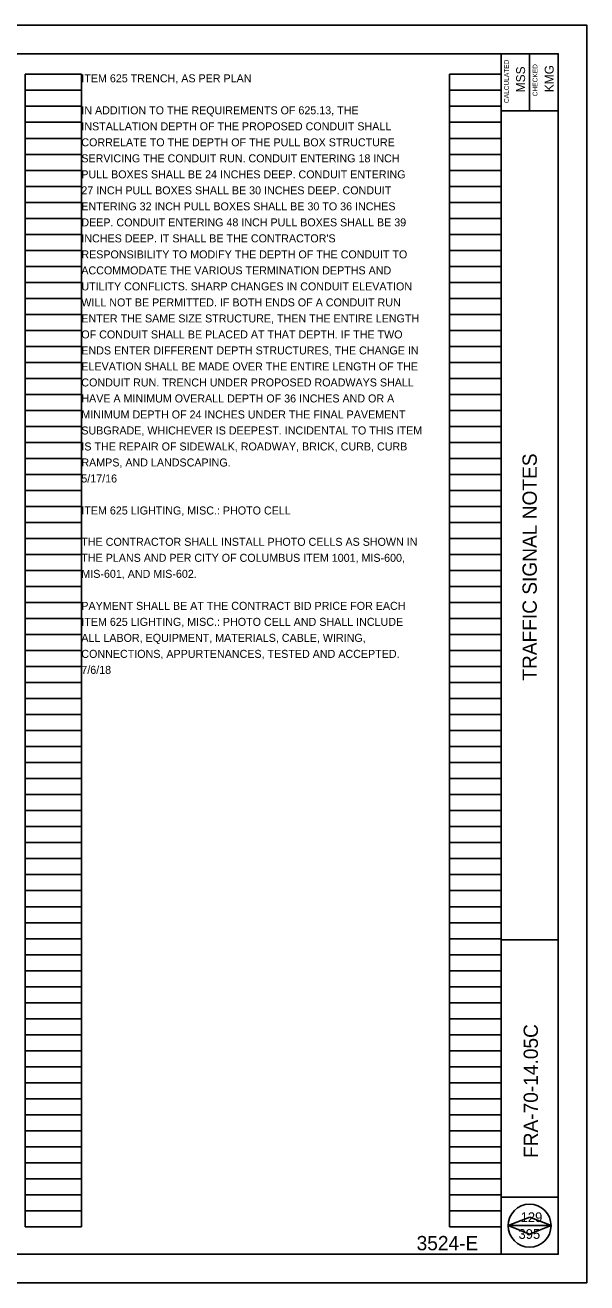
# Model space of a CAD drawing. Extents: x -25.6 to 66.7, y -23.1 to 37.2.
# Drawn here: x 23.67 to 33.49, y -7.51 to 14.49 of the extents above; entities that cross this region are included whole.
import ezdxf

# ---------------------------------------------------------------- set-up
doc = ezdxf.new("R2010")
doc.units = 0
for name, color, linetype in [('Level 63', 7, 'Continuous'), ('PF_P_Text', 7, 'Continuous'), ('SC_Scratch1', 7, 'Continuous'), ('SH_Cut_Line', 7, 'Continuous'), ('SH_Data', 7, 'Continuous'), ('SH_Text', 7, 'Continuous')]:
    doc.layers.add(name, color=color, linetype=linetype)

msp = doc.modelspace()

# ---------------------------------------------------------------- linework, layer by layer
at = {"layer": 'Level 63'}
msp.add_line((32.119, -6.508), (32.869, -6.508), dxfattribs=at)
msp.add_circle((32.494, -6.508), 0.375, dxfattribs=at)
at = {"layer": 'PF_P_Text'}
for p, q in [((31.994, -7.008), (31.994, 13.992)), ((32.494, 13.992), (32.494, 12.992)), ((31.994, 12.992), (32.994, 12.992)), ((31.994, -1.508), (32.994, -1.508)), ((31.994, -6.008), (32.994, -6.008))]:
    msp.add_line(p, q, dxfattribs=at)
msp.add_lwpolyline([(1.494, 13.992), (32.994, 13.992), (32.994, -7.008), (1.494, -7.008)], close=True, dxfattribs=at)
at = {"layer": 'SC_Scratch1'}
for p, q in [((23.674, -6.528), (23.674, 13.632)), ((23.674, 13.632), (24.654, 13.632)), ((24.654, -6.528), (24.654, 13.632)), ((31.094, -6.528), (31.094, 13.632)), ((31.094, 13.632), (31.994, 13.632)), ((31.994, -6.528), (31.994, 13.632)), ((23.674, 13.352), (24.654, 13.352)), ((31.094, 13.352), (31.994, 13.352)), ((23.674, 13.072), (24.654, 13.072)), ((31.094, 13.072), (31.994, 13.072)), ((23.674, 12.792), (24.654, 12.792)), ((31.094, 12.792), (31.994, 12.792)), ((23.674, 12.512), (24.654, 12.512)), ((31.094, 12.512), (31.994, 12.512)), ((23.674, 12.232), (24.654, 12.232)), ((31.094, 12.232), (31.994, 12.232)), ((23.674, 11.952), (24.654, 11.952)), ((31.094, 11.952), (31.994, 11.952)), ((23.674, 11.672), (24.654, 11.672)), ((31.094, 11.672), (31.994, 11.672)), ((23.674, 11.392), (24.654, 11.392)), ((31.094, 11.392), (31.994, 11.392)), ((23.674, 11.112), (24.654, 11.112)), ((31.094, 11.112), (31.994, 11.112)), ((23.674, 10.832), (24.654, 10.832)), ((31.094, 10.832), (31.994, 10.832)), ((23.674, 10.552), (24.654, 10.552)), ((31.094, 10.552), (31.994, 10.552)), ((23.674, 10.272), (24.654, 10.272)), ((31.094, 10.272), (31.994, 10.272)), ((23.674, 9.992), (24.654, 9.992)), ((31.094, 9.992), (31.994, 9.992)), ((23.674, 9.712), (24.654, 9.712)), ((31.094, 9.712), (31.994, 9.712)), ((23.674, 9.432), (24.654, 9.432)), ((31.094, 9.432), (31.994, 9.432)), ((23.674, 9.152), (24.654, 9.152)), ((31.094, 9.152), (31.994, 9.152)), ((23.674, 8.872), (24.654, 8.872)), ((31.094, 8.872), (31.994, 8.872)), ((23.674, 8.592), (24.654, 8.592)), ((31.094, 8.592), (31.994, 8.592)), ((23.674, 8.312), (24.654, 8.312)), ((31.094, 8.312), (31.994, 8.312)), ((23.674, 8.032), (24.654, 8.032)), ((31.094, 8.032), (31.994, 8.032)), ((23.674, 7.752), (24.654, 7.752)), ((31.094, 7.752), (31.994, 7.752)), ((23.674, 7.472), (24.654, 7.472)), ((31.094, 7.472), (31.994, 7.472)), ((23.674, 7.192), (24.654, 7.192)), ((31.094, 7.192), (31.994, 7.192)), ((23.674, 6.912), (24.654, 6.912)), ((31.094, 6.912), (31.994, 6.912)), ((23.674, 6.632), (24.654, 6.632)), ((31.094, 6.632), (31.994, 6.632)), ((23.674, 6.352), (24.654, 6.352)), ((31.094, 6.352), (31.994, 6.352)), ((23.674, 6.072), (24.654, 6.072)), ((31.094, 6.072), (31.994, 6.072)), ((23.674, 5.792), (24.654, 5.792)), ((31.094, 5.792), (31.994, 5.792)), ((23.674, 5.512), (24.654, 5.512)), ((31.094, 5.512), (31.994, 5.512)), ((23.674, 5.232), (24.654, 5.232)), ((31.094, 5.232), (31.994, 5.232)), ((23.674, 4.952), (24.654, 4.952)), ((31.094, 4.952), (31.994, 4.952)), ((23.674, 4.672), (24.654, 4.672)), ((31.094, 4.672), (31.994, 4.672)), ((23.674, 4.392), (24.654, 4.392)), ((31.094, 4.392), (31.994, 4.392)), ((23.674, 4.112), (24.654, 4.112)), ((31.094, 4.112), (31.994, 4.112)), ((23.674, 3.832), (24.654, 3.832)), ((31.094, 3.832), (31.994, 3.832)), ((23.674, 3.552), (24.654, 3.552)), ((31.094, 3.552), (31.994, 3.552)), ((23.674, 3.272), (24.654, 3.272)), ((31.094, 3.272), (31.994, 3.272)), ((23.674, 2.992), (24.654, 2.992)), ((31.094, 2.992), (31.994, 2.992)), ((23.674, 2.712), (24.654, 2.712)), ((31.094, 2.712), (31.994, 2.712)), ((23.674, 2.432), (24.654, 2.432)), ((31.094, 2.432), (31.994, 2.432)), ((23.674, 2.152), (24.654, 2.152)), ((31.094, 2.152), (31.994, 2.152)), ((23.674, 1.872), (24.654, 1.872)), ((31.094, 1.872), (31.994, 1.872)), ((23.674, 1.592), (24.654, 1.592)), ((31.094, 1.592), (31.994, 1.592)), ((23.674, 1.312), (24.654, 1.312)), ((31.094, 1.312), (31.994, 1.312)), ((23.674, 1.032), (24.654, 1.032)), ((31.094, 1.032), (31.994, 1.032)), ((23.674, 0.752), (24.654, 0.752)), ((31.094, 0.752), (31.994, 0.752)), ((23.674, 0.472), (24.654, 0.472)), ((31.094, 0.472), (31.994, 0.472)), ((23.674, 0.192), (24.654, 0.192)), ((31.094, 0.192), (31.994, 0.192)), ((23.674, -0.088), (24.654, -0.088)), ((31.094, -0.088), (31.994, -0.088)), ((23.674, -0.368), (24.654, -0.368)), ((31.094, -0.368), (31.994, -0.368)), ((23.674, -0.648), (24.654, -0.648)), ((31.094, -0.648), (31.994, -0.648)), ((23.674, -0.928), (24.654, -0.928)), ((31.094, -0.928), (31.994, -0.928)), ((23.674, -1.208), (24.654, -1.208)), ((31.094, -1.208), (31.994, -1.208)), ((23.674, -1.488), (24.654, -1.488)), ((31.094, -1.488), (31.994, -1.488)), ((23.674, -1.768), (24.654, -1.768)), ((31.094, -1.768), (31.994, -1.768)), ((23.674, -2.048), (24.654, -2.048)), ((31.094, -2.048), (31.994, -2.048)), ((23.674, -2.328), (24.654, -2.328)), ((31.094, -2.328), (31.994, -2.328)), ((23.674, -2.608), (24.654, -2.608)), ((31.094, -2.608), (31.994, -2.608)), ((23.674, -2.888), (24.654, -2.888)), ((31.094, -2.888), (31.994, -2.888)), ((23.674, -3.168), (24.654, -3.168)), ((31.094, -3.168), (31.994, -3.168)), ((23.674, -3.448), (24.654, -3.448)), ((31.094, -3.448), (31.994, -3.448)), ((23.674, -3.728), (24.654, -3.728)), ((31.094, -3.728), (31.994, -3.728)), ((23.674, -4.008), (24.654, -4.008)), ((31.094, -4.008), (31.994, -4.008)), ((23.674, -4.288), (24.654, -4.288)), ((31.094, -4.288), (31.994, -4.288)), ((23.674, -4.568), (24.654, -4.568)), ((31.094, -4.568), (31.994, -4.568)), ((23.674, -4.848), (24.654, -4.848)), ((31.094, -4.848), (31.994, -4.848)), ((23.674, -5.128), (24.654, -5.128)), ((31.094, -5.128), (31.994, -5.128)), ((23.674, -5.408), (24.654, -5.408)), ((31.094, -5.408), (31.994, -5.408)), ((23.674, -5.688), (24.654, -5.688)), ((31.094, -5.688), (31.994, -5.688)), ((23.674, -5.968), (24.654, -5.968)), ((31.094, -5.968), (31.994, -5.968)), ((23.674, -6.248), (24.654, -6.248)), ((31.094, -6.248), (31.994, -6.248)), ((32.119, -6.508), (32.495, -6.36)), ((32.495, -6.36), (32.869, -6.508)), ((23.674, -6.528), (24.654, -6.528)), ((31.094, -6.528), (31.994, -6.528)), ((32.49, -6.654), (32.119, -6.508)), ((32.869, -6.508), (32.49, -6.654))]:
    msp.add_line(p, q, dxfattribs=at)
at = {"layer": 'SH_Cut_Line'}
msp.add_lwpolyline([(-0.506, -7.508), (33.494, -7.508), (33.494, 14.492), (-0.506, 14.492)], close=True, dxfattribs=at)

# ---------------------------------------------------------------- texts
at = {"layer": 'Level 63'}
for s, height, p in [('CALCULATED', 0.0833, (32.13, 13.129)), ('MSS', 0.156, (32.414, 13.317)), ('CHECKED', 0.0833, (32.63, 13.248)), ('KMG', 0.156, (32.914, 13.319)), ('TRAFFIC SIGNAL NOTES', 0.25, (32.619, 3.025)), ('FRA-70-14.05C', 0.25, (32.639, -5.324))]:
    msp.add_text(s, height=height, rotation=90, dxfattribs=at).set_placement(p)
at = {"layer": 'SH_Data'}
msp.add_text('3524-E', height=0.25, rotation=359.9999, dxfattribs=at).set_placement((30.517, -6.938))
at = {"layer": 'SH_Text'}
for s, height, p in [('ITEM 625 TRENCH, AS PER PLAN', 0.14, (24.654, 13.492)), ('IN ADDITION TO THE REQUIREMENTS OF 625.13, THE ', 0.14, (24.654, 12.932)), ('INSTALLATION DEPTH OF THE PROPOSED CONDUIT SHALL ', 0.14, (24.654, 12.652)), ('CORRELATE TO THE DEPTH OF THE PULL BOX STRUCTURE ', 0.14, (24.654, 12.372)), ('SERVICING THE CONDUIT RUN. CONDUIT ENTERING 18 INCH ', 0.14, (24.654, 12.092)), ('PULL BOXES SHALL BE 24 INCHES DEEP. CONDUIT ENTERING ', 0.14, (24.654, 11.812)), ('27 INCH PULL BOXES SHALL BE 30 INCHES DEEP. CONDUIT ', 0.14, (24.654, 11.532)), ('ENTERING 32 INCH PULL BOXES SHALL BE 30 TO 36 INCHES ', 0.14, (24.654, 11.252)), ('DEEP. CONDUIT ENTERING 48 INCH PULL BOXES SHALL BE 39 ', 0.14, (24.654, 10.972)), ("INCHES DEEP. IT SHALL BE THE CONTRACTOR'S ", 0.14, (24.654, 10.692)), ('RESPONSIBILITY TO MODIFY THE DEPTH OF THE CONDUIT TO ', 0.14, (24.654, 10.412)), ('ACCOMMODATE THE VARIOUS TERMINATION DEPTHS AND ', 0.14, (24.654, 10.132)), ('UTILITY CONFLICTS. SHARP CHANGES IN CONDUIT ELEVATION ', 0.14, (24.654, 9.852)), ('WILL NOT BE PERMITTED. IF BOTH ENDS OF A CONDUIT RUN ', 0.14, (24.654, 9.572)), ('ENTER THE SAME SIZE STRUCTURE, THEN THE ENTIRE LENGTH ', 0.14, (24.654, 9.292)), ('OF CONDUIT SHALL BE PLACED AT THAT DEPTH. IF THE TWO ', 0.14, (24.654, 9.012)), ('ENDS ENTER DIFFERENT DEPTH STRUCTURES, THE CHANGE IN ', 0.14, (24.654, 8.732)), ('ELEVATION SHALL BE MADE OVER THE ENTIRE LENGTH OF THE ', 0.14, (24.654, 8.452)), ('CONDUIT RUN. TRENCH UNDER PROPOSED ROADWAYS SHALL ', 0.14, (24.654, 8.172)), ('HAVE A MINIMUM OVERALL DEPTH OF 36 INCHES AND OR A ', 0.14, (24.654, 7.892)), ('MINIMUM DEPTH OF 24 INCHES UNDER THE FINAL PAVEMENT ', 0.14, (24.654, 7.612)), ('SUBGRADE, WHICHEVER IS DEEPEST. INCIDENTAL TO THIS ITEM ', 0.14, (24.654, 7.332)), ('IS THE REPAIR OF SIDEWALK, ROADWAY, BRICK, CURB, CURB ', 0.14, (24.654, 7.052)), ('RAMPS, AND LANDSCAPING. ', 0.14, (24.654, 6.772)), ('5/17/16', 0.14, (24.654, 6.492)), ('ITEM 625 LIGHTING, MISC.: PHOTO CELL', 0.14, (24.654, 5.932)), ('THE CONTRACTOR SHALL INSTALL PHOTO CELLS AS SHOWN IN ', 0.14, (24.654, 5.384)), ('THE PLANS AND PER CITY OF COLUMBUS ITEM 1001, MIS-600, ', 0.14, (24.654, 5.104)), ('MIS-601, AND MIS-602.', 0.14, (24.654, 4.824)), ('PAYMENT SHALL BE AT THE CONTRACT BID PRICE FOR EACH ', 0.14, (24.654, 4.264)), ('ITEM 625 LIGHTING, MISC.: PHOTO CELL AND SHALL INCLUDE ', 0.14, (24.654, 3.984)), ('ALL LABOR, EQUIPMENT, MATERIALS, CABLE, WIRING, ', 0.14, (24.654, 3.704)), ('CONNECTIONS, APPURTENANCES, TESTED AND ACCEPTED.', 0.14, (24.654, 3.424)), ('7/6/18', 0.14, (24.654, 3.144)), ('129', 0.17, (32.336, -6.445)), ('395', 0.17, (32.299, -6.739))]:
    msp.add_text(s, height=height, dxfattribs=at).set_placement(p)

doc.saveas('drawing.dxf')
